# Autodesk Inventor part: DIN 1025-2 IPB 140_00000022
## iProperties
Created: 2006-02
Part Number: DIN 1025-2 IPB 140_00000022
Material: Default
Document SubType Name: Modeling
Designer: 40664
Manufacturer: Standard
Standards Organization: Custom
Stock Number: DIN 1025-2 IPB 140
Mass: 15507.1 g
Surface Area: 29196.4 cm^2
Volume: 15507.1 cm^3
Density: 1 g/cm^3
G_L: 3750.000 mm
G_W: 140.000 mm
G_H: 140.000 mm
AFG_Item: IPB 140
CSToolsMass: 16.0
CSToolsVolume: 15507088.0
CSToolsArea: 29196.0
Author: 40664
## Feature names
1. AFG_Detailed_DIN 1025-2 IPB 140_00000022 [Extrusion]
2. AFG_Simplified_DIN 1025-2 IPB 140_00000022 [Extrusion]
